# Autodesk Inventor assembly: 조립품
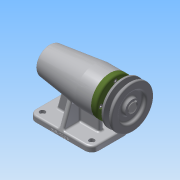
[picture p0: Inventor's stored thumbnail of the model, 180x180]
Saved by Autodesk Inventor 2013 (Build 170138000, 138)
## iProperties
Created: 2018-09
Part Number: 조립품
Document SubType Name: Assembly
Designer: Administrator
Author: Administrator
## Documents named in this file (12)
- C:\Users\Administrator\Desktop\480908V1010\답안 조립품.iam
- C:\Users\Administrator\Desktop\480908V1010\본체.ipt
- C:\Users\Administrator\Desktop\480908V1010\축.ipt
- C:\Users\Administrator\Desktop\480908V1010\베어링 6004.ipt
- C:\Users\Administrator\Desktop\480908V1010\어댑터슬리브.ipt
- C:\Users\Administrator\Desktop\480908V1010\볼트 M4.ipt
- C:\Users\Administrator\Desktop\480908V1010\베어링 51202.ipt
- C:\Users\Administrator\Desktop\480908V1010\커버.ipt
- C:\Users\Administrator\Desktop\480908V1010\오일 실.ipt
- C:\Users\Administrator\Desktop\480908V1010\멈춤나사 M3.ipt
- C:\Users\Administrator\Desktop\480908V1010\키 5 x 5 x 16.ipt
- C:\Users\Administrator\Desktop\480908V1010\V벨트풀리.ipt
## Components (1 placed, 1 different names)
1. V벨트풀리:1
